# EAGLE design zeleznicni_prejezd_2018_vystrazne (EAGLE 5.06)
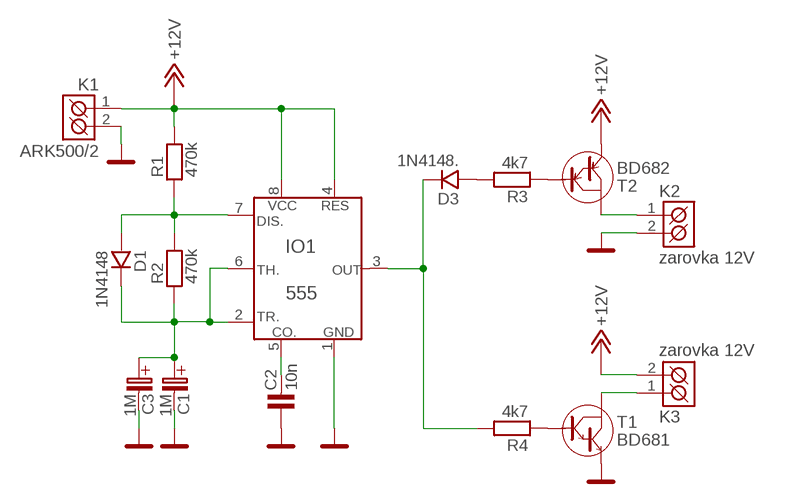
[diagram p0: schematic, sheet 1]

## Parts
C1  1M  1M/50V  [C_EL_2]
C2  10n  C-KER_1206  [1206]
C3  1M  1M/50V  [C_EL_2]
D1  1N4148  1N4148.  [SOD-80]
D3  1N4148.  [SOD-80]
IO1  555  [DIL8]
K1  ARK500/2  [ARK500/2]
K2  zarovka 12V  ARK500/2  [ARK500/2]
K3  zarovka 12V  ARK500/2  [ARK500/2]
R1  470k  R_1206  [1206]
R2  470k  R_1206  [1206]
R3  4k7  R_1206  [1206]
R4  4k7  R_1206  [1206]
T1  BD681  [TO-126S]
T2  BD682  [TO-126S]

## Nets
+12V: IO1.4(RES) IO1.8(VCC) K1.1(K1) K3.2(K2) R1.2 T2.1(E)
GND: C1.C-(C_EL-) C2.1 C3.C-(C_EL-) IO1.1(GND) K1.2(K2) K2.2(K2) T1.1(E)
N$1: C1.C+(C_EL+) C3.C+(C_EL+) D1.K IO1.2(TR.) IO1.6(TH.) R2.1
N$2: D1.A IO1.7(DIS.) R1.1 R2.2
N$3: R3.1 T2.3(B)
N$4: D3.A R3.2
N$6: K2.1(K1) T2.2(C)
N$7: D3.K IO1.3(OUT) R4.2
N$8: K3.1(K1) T1.2(C)
N$9: R4.1 T1.3(B)
N$10: C2.2 IO1.5(CO.)

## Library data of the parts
C1 C3 = #PaJa_C-el_2:1M/50V
C2 = #PaJa_32:C-KER: Kondenzator - keramicky
D1 D3 = #PaJa_32:1N4148: Univerzalni dioda - 0,15A, 75V
IO1 = #PaJa_32:555: IO - Casovac 555
K1-K3 = #PaJa_konektory:ARK500/2: Svorkovnice - roztec 5mm - dvojita
R1-R4 = #PaJa_32:R: Rezistor
T1 = #PaJa_32:BD681: Tranzistor NPN - Darlington, 100V, 4A
T2 = #PaJa_32:BD682: Tranzistor PNP - Darlington, 100V, 4A

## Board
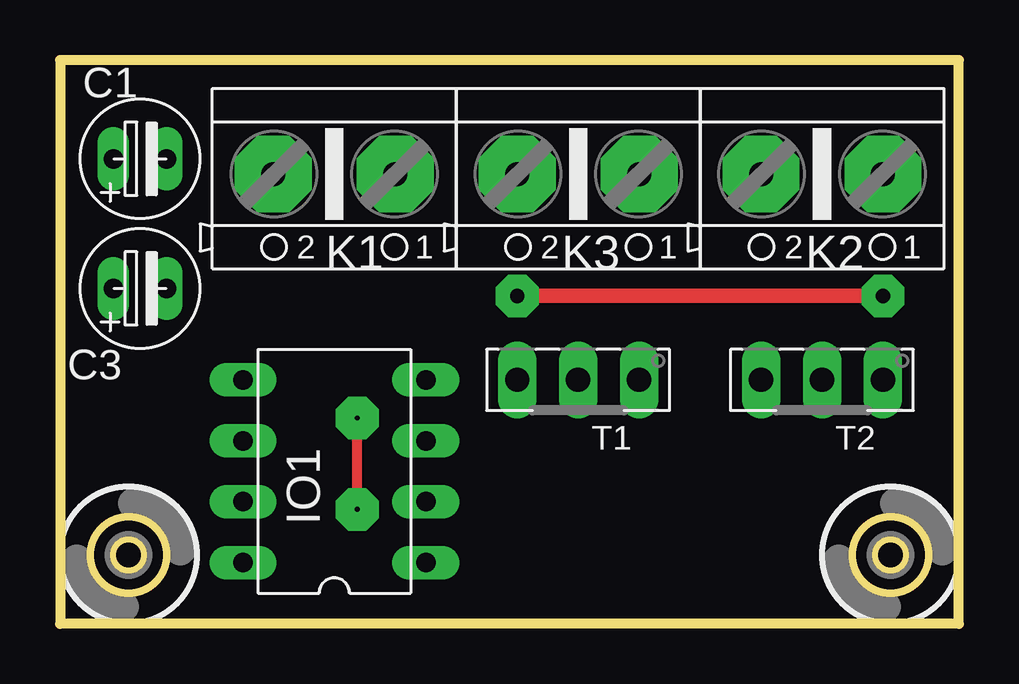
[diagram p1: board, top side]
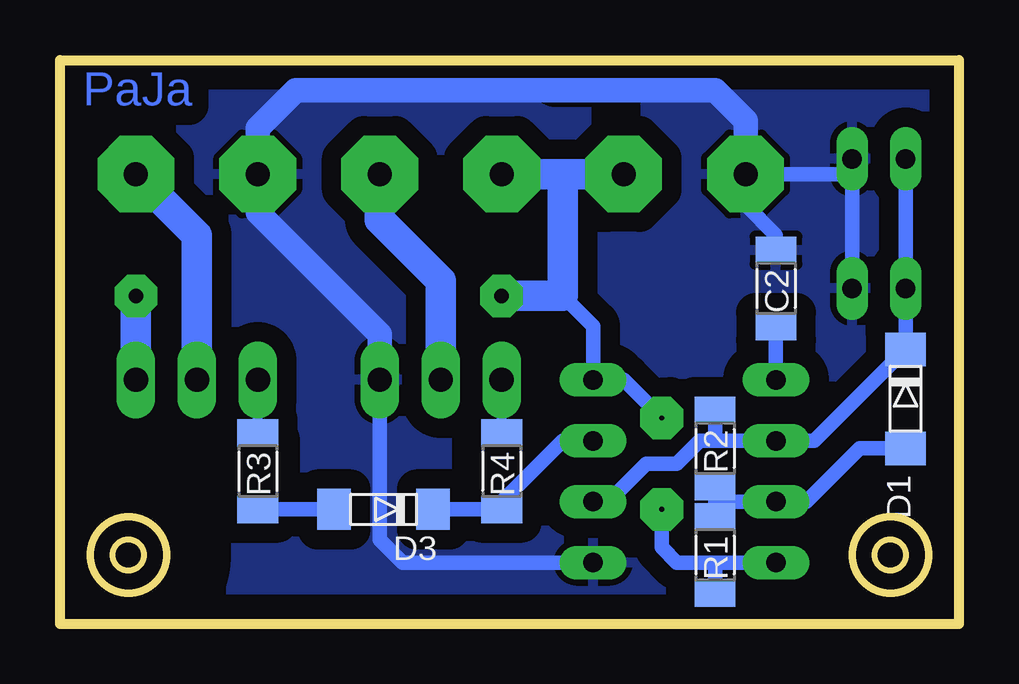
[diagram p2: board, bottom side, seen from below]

Size 37.45 x 23.5 mm. Coordinates in mm from the lower left corner, seen from the top.
Outline: 0,23.5 0,0 37.45,0 37.45,23.5 0,23.5
Copper layers (1*16): Top 0.035mm / dielectric 1.5mm / Bottom 0.035mm
Design rules "default": minimum track width 10mil, minimum drill 24mil, track to track 8mil, track to pad 8mil, pad to pad 8mil, via to via 8mil, smd to smd 8mil, copper to edge 40mil, drill to drill 8mil, minimum pad ring 10mil, minimum via ring 8mil, stop-mask expansion 4mil, vias tented up to drill 0mil, thermal gap 10mil
bRestrict: 5 lines

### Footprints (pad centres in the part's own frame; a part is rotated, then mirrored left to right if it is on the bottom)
C_EL_2 = drill 0.813 pad 1.27 long: C+ 0,0; C- 2.223,0
1206 = smd 1.143 x 1.702: 1 -1.587,0; 2 1.587,0
SOD-80 = smd 1.397 x 1.702: A 1.905,0; K -2.223,0
DIL8 = drill 0.813 pad 1.4 long: 1 -3.81,-3.81; 2 -1.27,-3.81; 3 1.27,-3.81; 4 3.81,-3.81; 5 3.81,3.81; 6 1.27,3.81; 7 -1.27,3.81; 8 -3.81,3.81
ARK500/2 = drill 1 pad 3.2 octagon: 1 -2.54,0; 2 2.54,0
TO-126S = drill 1.016 pad 1.6 long: 1 -2.54,0; 2 0,0; 3 2.54,0
HOLE_3,0 = hole 3.2: 0,0

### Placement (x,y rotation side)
C1  2.22,19.38 0 top
C2  7.62,13.98 270 bottom
C3  2.22,13.98 0 top
D1  2.22,9.22 270 bottom
D3  24.13,4.77 180 bottom
IO1  11.43,6.36 90 top
K1  11.43,18.74 180 top
K2  31.75,18.74 180 top
K3  21.59,18.74 180 top
R1  10.16,2.87 270 bottom
R2  10.16,7.31 270 bottom
R3  29.21,6.36 270 bottom
R4  19.05,6.36 270 bottom
T1  21.59,10.17 180 top
T2  31.75,10.17 180 top
U$1  [HOLE_3,0]  2.86,2.87 0 top
U$3  [HOLE_3,0]  34.61,2.87 0 top

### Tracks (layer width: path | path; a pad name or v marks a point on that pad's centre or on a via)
+12V  (via drill 0.2 pad 1.78, 0.6 pad 1.78)
  Top 0.406: v12.38,4.77 v12.38,8.58
  Top 0.61: v19.05,13.66 v34.29,13.66
  Bottom 0.61: 10.16,2.55 11.75,2.55 12.38,3.18 v12.38,4.77 | 10.16,2.55 IO1.8 | R1.2 10.16,2.55 | v12.38,8.58 13.97,10.17 IO1.4 15.24,12.39 16.51,13.66
  Bottom 1.27: 16.51,18.74 K1.1 | 16.51,18.74 16.51,13.66 v19.05,13.66 | 16.51,18.74 K3.2 | v34.29,13.66 T2.1
GND
  Bottom 0.406: K1.2 8.89,17.47
  Bottom 0.61: T1.1 24.13,3.5 23.18,2.55 IO1.1 | K1.2 4.45,18.74 C1.C- C3.C- | 8.89,17.47 7.62,16.2 C2.1
  Bottom 1.016: T1.1 24.13,12.07 29.21,17.16 K2.2 29.21,20.65 27.62,22.24 10.16,22.24 8.89,20.96 K1.2
  pour Bottom (isolate 0.813): 0,23.51 0,0.01 37.47,0.01 37.47,23.51
N$1
  Bottom 0.61: 10.16,7.63 IO1.6 6.03,7.63 D1.K C3.C+ C1.C+ | 10.16,7.63 R2.1 | 10.16,7.63 10.79,7.63 11.75,6.68 13.02,6.68 14.61,5.09 IO1.2
N$2
  Bottom 0.61: 10.16,5.09 IO1.7 6.35,5.09 4.13,7.31 D1.A | 10.16,5.09 R2.2 | 10.16,5.09 R1.1
N$3
  Bottom 0.406: R3.1 T2.3
N$4
  Bottom 0.61: D3.A R3.2
N$6
  Bottom 1.27: K2.1 31.75,16.2 T2.2
N$7
  Bottom 0.406: R4.2 19.05,5.09
  Bottom 0.61: IO1.3 16.51,7.63 19.05,5.09 | R4.2 D3.K
N$8
  Bottom 1.27: K3.1 24.13,16.84 21.59,14.3 T1.2
N$9
  Bottom 0.406: R4.1 T1.3
N$10
  Bottom 0.61: IO1.5 C2.2

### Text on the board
Bottom: PaJa
PaJa: www.paja-trb.cz
wago-cervena: 0R | 0R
